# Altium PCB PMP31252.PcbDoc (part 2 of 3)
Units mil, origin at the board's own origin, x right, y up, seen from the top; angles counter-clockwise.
Board outline 4527.56 x 3188.98 mil, 6 copper layers (Top Layer, Layer 1, Layer 3, Layer 4, Layer 2, Bottom Layer), stack 32.112 mil thick; 215 components, 83 nets, 499 pads, 1248 vias.
Unrouted connection lines stored in the file: 2.
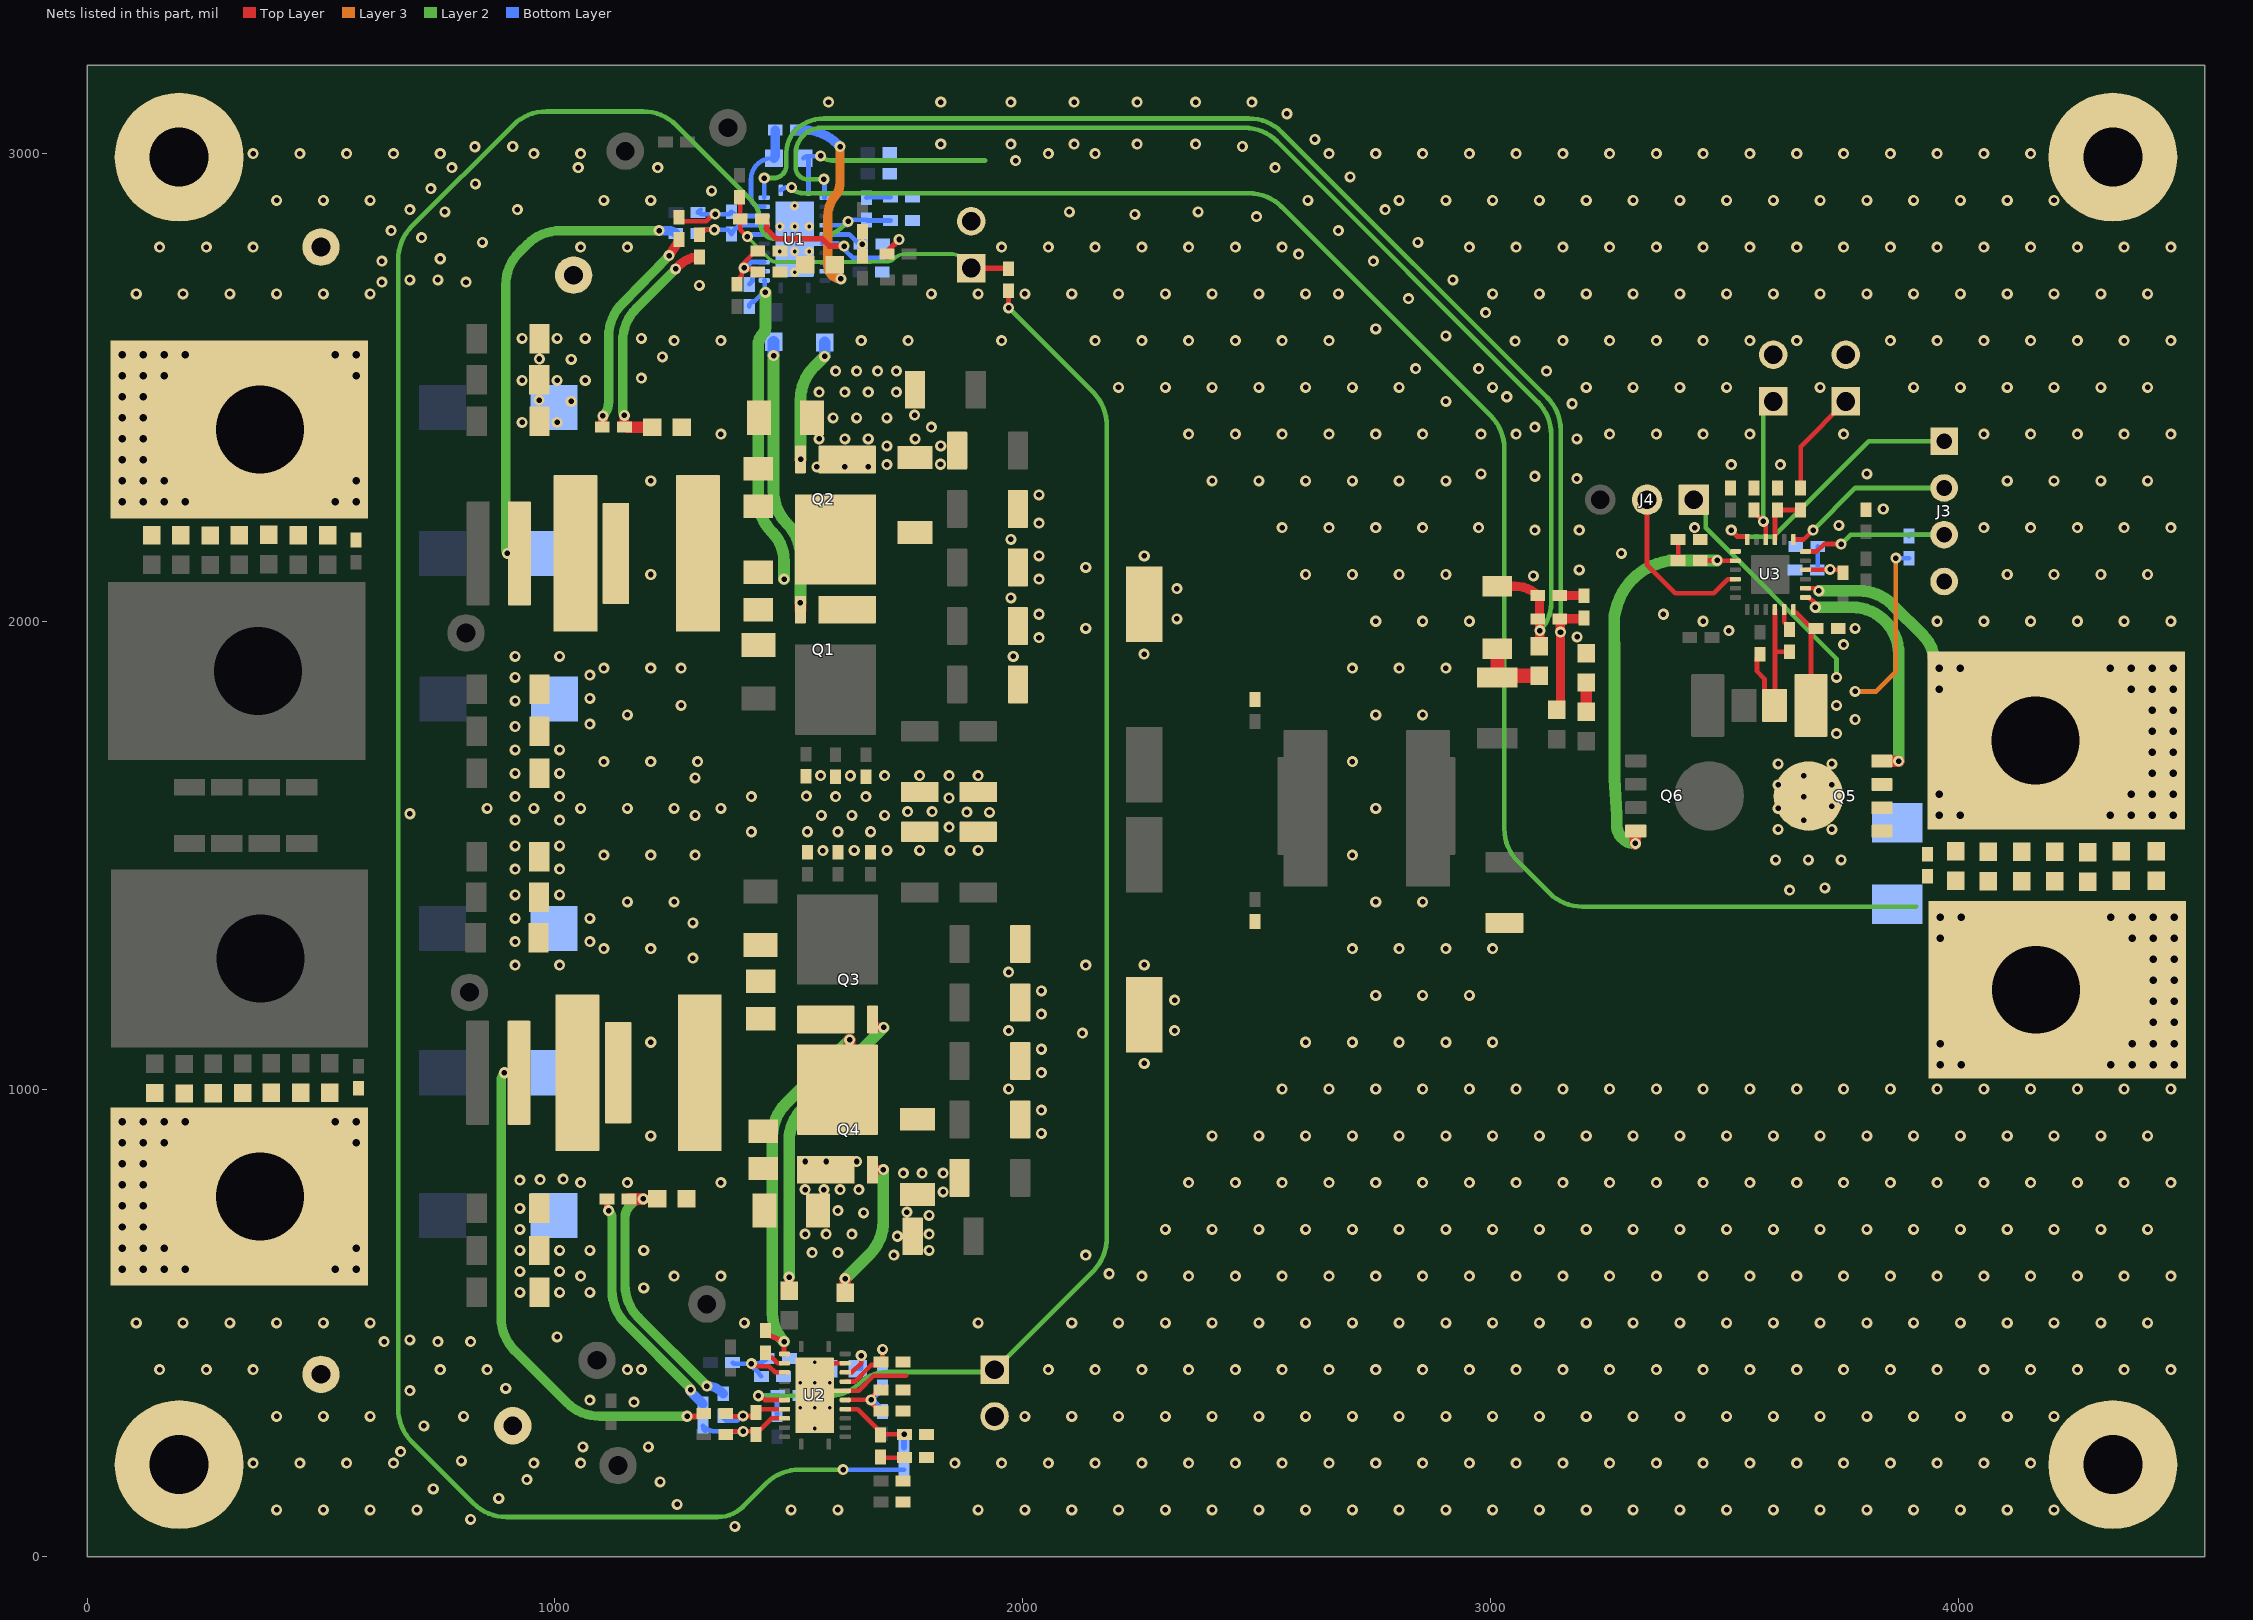
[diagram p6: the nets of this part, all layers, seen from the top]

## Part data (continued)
R24: library part CMP-0026619-3, "RES, 9.09 k, 1%, 0.063 W, AEC-Q200 Grade 0, 0402", Manufacturer=Vishay-Dale, Power_W=63mW, Supplier Part Number 1=541-9.09KLCT-ND, TempCo="100 ppm/C", Tolerance_%=1%, Value2=0.063W, Value_Code=9k09, ValueDisplayed=9.09k
R26 R27 R28 R29: library part CMP-0017276-1, "RES, 0, 1%, 0.25 W, 1206", Manufacturer="State of the Art", Power_W=250mW, TempCo="25 ppm/C", Tolerance_%=1%, Value2=0.25W, Value_Code=0
R30 R31 R32 R34: library part CMP-0017853-2, "RES, 110, 1%, 0.25 W, 1206", Manufacturer="Yageo America", Power_W=250mW, Supplier Part Number 1=311-110FRCT-ND, TempCo="100 ppm/C", Tolerance_%=1%, Value2=0.25W, Value_Code=110R, ValueDisplayed=110
R39 R59 R60 R61: library part CMP-0026753-1, "RES, 100 k, 1%, 0.063 W, AEC-Q200 Grade 0, 0402", Manufacturer="Stackpole Electronics Inc", Power_W=63mW, Supplier Part Number 1=RMCF0402FT100KCT-ND, TempCo="100 ppm/C", Tolerance_%=1%, Value2=0.063W, Value_Code=100k
R46: library part CMP-0026703-1, "RES, 49.9, 1%, 0.1 W, AEC-Q200 Grade 0, 0402", Manufacturer=Panasonic, Power_W=100mW, Supplier Part Number 1=P49.9LCT-ND, TempCo="100 ppm/C", Tolerance_%=1%, Value2=0.1W, Value_Code=49R9, ValueDisplayed=DNP
R47: library part CMP-0026605-2, "RES, 90.9 k, 1%, 0.063 W, AEC-Q200 Grade 0, 0402", Manufacturer=Vishay-Dale, Power_W=63mW, Supplier Part Number 1=541-90.9KLCT-ND, TempCo="100 ppm/C", Tolerance_%=1%, Value2=0.063W, Value_Code=90k9, ValueDisplayed=90.9k
R50 R53: library part CMP-0026196-2, "RES, 24.9 k, 1%, 0.063 W, AEC-Q200 Grade 0, 0402", Manufacturer=Vishay-Dale, Power_W=63mW, Supplier Part Number 1=541-24.9KLCT-ND, TempCo="100 ppm/C", Tolerance_%=1%, Value2=0.063W, Value_Code=24k9, ValueDisplayed=DNP
R55: library part CMP-0026685-1, "RES, 2.40 k, 1%, 0.1 W, AEC-Q200 Grade 0, 0402", Manufacturer=Panasonic, Power_W=100mW, Supplier Part Number 1=P2.40KLCT-ND, TempCo="100 ppm/C", Tolerance_%=1%, Value2=0.1W, Value_Code=2k40, ValueDisplayed=2.40k
R56: library part CMP-0093189-1, "500 µOhms ±1% 1W Chip Resistor 0805 (2012 Metric) Automotive AEC-Q200, Current Sense Metal Element", Digikey Part Number=738-CSSH0805FTL500CT-ND, Manufacturer="Stackpole Electronics", Operating Temperature Range="-55°C to +170°C", Power_W=1W, TempCo=100ppm/°C, Tolerance_%=1%
R57: library part CMP-0026763-1, "RES, 100, 1%, 0.063 W, AEC-Q200 Grade 0, 0402", Manufacturer="Stackpole Electronics Inc", Power_W=63mW, Supplier Part Number 1=RMCF0402JT100RCT-ND, TempCo="100 ppm/C", Tolerance_%=1%, Value2=0.063W, Value_Code=100R, ValueDisplayed=100
R62: library part CMP-0026092-3, "RES, 1.65 k, 1%, 0.063 W, AEC-Q200 Grade 0, 0402", Manufacturer=Vishay-Dale, Power_W=63mW, Supplier Part Number 1=541-1.65KLCT-ND, TempCo="100 ppm/C", Tolerance_%=1%, Value2=0.063W, Value_Code=1k65, ValueDisplayed=1.65k
R63: library part CMP-0025977-3, "RES, 11.5 k, 1%, 0.063 W, AEC-Q200 Grade 0, 0402", Manufacturer=Vishay-Dale, Power_W=63mW, Supplier Part Number 1=541-11.5KLCT-ND, TempCo="100 ppm/C", Tolerance_%=1%, Value2=0.063W, Value_Code=11k5, ValueDisplayed=11.5k
R65 R66: library part CMP-0078244-2, "RES, 30.0 k, 1%, 0.063 W, AEC-Q200 Grade 0, 0402", Manufacturer=Vishay-Dale, Power_W=63mW, Supplier Part Number 1=541-30.0KLCT-ND, TempCo="100 ppm/C", Tolerance_%=1%, Value2=0.063W, Value_Code=30k0, ValueDisplayed=30.0k
R68: library part CMP-0092536-1, "1 mOhms ±1% 3W Chip Resistor 2512 (6432 Metric) Automotive AEC-Q200, Current Sense, Moisture Resistant Metal Element", Digikey Part Number=HCS2512FT1L00CT-ND, Manufacturer="Stackpole Electronics", Operating Temperature Range="-55°C to +170°C", Power_W=3W, TempCo=100ppm/°C, Tolerance_%=1%
R69: library part CMP-0022716-3, "RES, 0.47, 1%, 0.1 W, AEC-Q200 Grade 0, 0603", Manufacturer=Panasonic, Power_W=100mW, Supplier Part Number 1=P.47AJCT-ND, TempCo="300 ppm/C", Tolerance_%=1%, Value2=0.1W, Value_Code=R470, ValueDisplayed=0.47
T1 T2 T3 T4 T5 T6: library part CMP-0055442-1, "Terminal 50A Lug", Manufacturer=Panduit, Supplier Part Number 1=CB35-36-CY-ND, Voltage_V=600V
TP1 TP5 TP8 TP10: library part CMP-0055137-2, "Test Point, Miniature, Red, TH", Color=Red, Manufacturer="Keystone Electronics", Supplier Part Number 1=36-5000-ND
TP2 TP6: library part CMP-0055141-2, "Test Point, Miniature, Yellow, TH", Color=Yellow, Manufacturer="Keystone Electronics", Supplier Part Number 1=36-5004-ND
TP3 TP7 TP9 TP11: library part CMP-0055138-2, "Test Point, Miniature, Black, TH", Color=Black, Manufacturer="Keystone Electronics", Supplier Part Number 1=36-5001-ND
TP4: library part CMP-0055140-2, "Test Point, Miniature, Orange, TH", Color=Orange, Manufacturer="Keystone Electronics", Supplier Part Number 1=36-5003-ND
U1 U2: library part CMP-0092804-1, "Automotive Synchronous Buck DC/DC Controller with Ultra-Low IQ, Adjustable, 0.8-36V, VQFN24", Manufacturer="Texas Instruments", Max Supply Voltage=42V, Min Supply Voltage=3.5V, Operating Temperature Range="-40°C to +150°C", Output Voltage=0.8-36V, Switching Frequency=100-2200kHz
U3: library part CMP-0001363-1, "Ideal Diode Controller with Integrated Short Circuit Protection with Fault Output", Manufacturer="Texas Instruments", Max Supply Voltage=65V, Min Supply Voltage=3V, Nominal Supply Current=550-600uA, Operating Temperature Range="-40°C to +150°C"

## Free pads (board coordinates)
  round 275.59 hole 125.98: 6(196.85,196.85) 6(196.85,2992.13) 6(4330.71,196.85) 6(4330.71,2992.13)

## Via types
v1: diameter 23.62, hole 11.81, Top Layer to Bottom Layer, tented both sides, 1061 vias
v2: diameter 32, hole 16, Top Layer to Bottom Layer, 168 vias
v3: diameter 19.68, hole 7.87, Top Layer to Bottom Layer, 16 vias
v4: diameter 23.62/23.62/23.62/23.62/23.62/23.62 (per signal layer), hole 11.81, Top Layer to Bottom Layer, tented both sides, 3 vias

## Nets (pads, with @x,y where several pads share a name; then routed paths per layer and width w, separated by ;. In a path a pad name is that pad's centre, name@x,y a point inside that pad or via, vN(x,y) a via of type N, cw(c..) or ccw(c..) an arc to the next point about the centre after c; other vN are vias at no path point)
AGND1: C24.2 C25.2 C26.2 NT3.1 R18.1 R19.1 R20.1 R21.1 R24.1 U1.7 | length 393.9
  Top Layer w12: R18.1@1443.62,2860 1447.56,2860 1453.37,2854.19 1453.37,2837.91 1473.78,2817.5 1571.45,2817.5 1586.75,2802.2 v1(1618.34,2802.2) ; R21.1@1710,2785 cw(c1722.07,2785) 1713.54,2793.54 v1(1736.16,2816.16)
  Layer 2 w10: v1(1618.34,2802.2) 1618.34,2805.65 cw(c1619.3,2805.65) v1@1619.3,2806.61
  Layer 3 w10: v1(1736.16,2816.16) cw(c1737.21,2815.11) v1@1737.21,2816.59
  Bottom Layer w10: NT3.1@1571.75,2807.44 1605.94,2807.44 ; v1(1618.34,2802.2) 1618.34,2803.51 1622.39,2803.51 1622.39,2790.98 1636.68,2776.69 1702.52,2776.69
AGND2: C45.2 C46.2 C47.2 NT4.1 R45.1 R47.1 R48.1 R53.2 U2.7 | length 149.2
  Top Layer w10: NT4.1@1614.76,355.09 1649.5,355.09 1681.19,386.77 1750.87,386.77
COMP2: C46.1 R54.2 R55.2 U2.5 | length 182.1
  Top Layer w10: U2.5@1620.83,315.47 1647.51,315.47 1689.06,273.93 1689.06,267.2 R55.2@1695.87,260.39 1697.24,261.77 C46.1@1747.24,261.77
  Bottom Layer w12: R54.2@1746.32,233.52 1746.32,260.2 cw(c1748.45,260.2) v1(1746.95,261.7)
ENABLE: J2.1 R33.1 R35.2 R67.2 U2.19 | length 3136.3
  Top Layer w10: v1@1442.99,341.57 1449.41,335.16 U2.19@1490.91,335.16 ; v1(1970,2670) R35.2@1970,2706.38
  Layer 2 w10: v1(1434.89,344.18) 1587.67,344.18 ccw(c1587.67,432.33) 1650,370 cw(c1710.36,309.64) 1710.36,395 1929.66,395 cw(c1929.66,382.27) J2.1@1938.66,391.27 ; J2.1@1940,400 2150.71,610.71 ccw(c2080,681.42) 2180,681.42 2180,2418.58 ccw(c2080,2418.58) 2150.71,2489.29 v1(1970,2670)
  Bottom Layer w10: v1(1434.89,344.18) 1435.3,344.59 R67.2@1475.97,344.59 ; R33.1@1475,303.62 1475,343.62 R67.2@1475.97,344.59 ; R67.2@1476.38,345 R67.2@1475.97,344.59
EXTCOMP: C24.1 R14.2 R54.1 U1.5 | length 5086.4
  Layer 2 w10: v1(1616.27,186.28) 1522.7,186.28 ccw(c1522.7,86.28) 1451.99,156.99 1402.5,107.5 cw(c1348.18,161.82) 1348.18,85 896.42,85 cw(c896.42,185) 825.71,114.29 694.29,245.71 cw(c765,316.42) 665,316.42 665,2773.58 cw(c765,2773.58) 694.29,2844.29 910.71,3060.71 cw(c981.42,2990) 981.42,3090 1188.58,3090 cw(c1188.58,2990) 1259.29,3060.71 1418.79,2901.21 cw(c1367.57,2850) 1440,2850 1440,2848.14 ccw(c1470.44,2848.14) 1470.44,2817.69 1548.34,2817.69 ccw(c1548.34,2917.69) 1619.05,2846.98 v1(1626.8,2854.74) ccw(c1623.53,2858.01) v1@1628.16,2858.01
  Bottom Layer w10: U1.5@1577.52,2846.69 1625,2846.69 ccw(c1617.38,2854.31) 1628.16,2854.31 1627.45,2854.53 v1(1626.8,2854.74) 1630.49,2854.74 1633.82,2858.07 R14.2@1666.14,2858.07 1667.52,2856.69 C24.1@1717.52,2856.69 ; v1(1616.27,186.28) R54.1@1746.32,186.28
FB1: R13.1 R16.1 R24.2 U1.6 | length 133.6
  Top Layer w10: R13.1@1657.52,2780.31 v1(1657.52,2805.91) R16.1@1657.52,2833.07
  Bottom Layer w10: U1.6@1577.52,2827.01 1629.65,2827.01 v1@1649.96,2806.69
FB2: R43.2 R45.2 R50.2 R53.1 U2.6 | length 188
  Top Layer w10: U2.6@1627.64,335.24 1627.77,335.37 v1(1675.89,335.37) ; R45.2@1693.31,311.77 1678.5,326.58 1678.5,332.76 v1(1675.89,335.37) ; R53.1@1697.07,356.71 1693.13,356.71 1678.5,342.07 1678.5,337.98 v1(1675.89,335.37)
  Bottom Layer w10: R50.2@1700.87,310.39 1700.87,314.33 1682.43,332.76 1678.5,332.76 v1(1675.89,335.37) 1677.02,335.37 1700.87,359.21 R43.2@1700.87,363.15
GND: C1.2 C2.1 C3.1 C4.1 C5.1 C6.1 C7.1 C8.1 C9.2 C16.2 C18.2 C19.2 C20.2 C21.2 C22.2 C27.2 C28.1 C29.1 C30.1 C31.1 C32.1 C33.1 C34.1 C36.1 C38.2 C39.2 C40.2 C41.2 C42.2 C43.2 C48.2 C49.2 C51.2 C52.2 C53.2 C54.1 C56.1 C57.2 C58.2 C59.2 C60.2 C61.2 C62.2 C63.2 C64.2 C65.2 C66.2 C67.2 C68.2 C69.2 C70.2 C71.2 C72.2 C73.2 C78.2 C79.2 C80.2 C81.2 C82.2 C83.2 C84.2 C85.2 C86.2 C87.2 C88.2 C89.2 C90.2 C91.2 C92.2 C93.2 C94.2 C95.2 C96.2 C97.2 C98.2 C99.2 C101.2 D1.2 D2.2 D3.1 J1.2 J2.2 J3.4 J5.2 J6.2 NT1.2 NT2.2 NT3.2 NT4.2 pad.6 Q2.1-2-3 Q4.1-2-3 R11.1 R31.1 R34.1 R42.1 R62.1 R63.1 R65.1 R66.1 R67.1 R69.1 T2.1 T4.1 T6.1 TP3.1 TP7.1 TP9.1 TP11.1 U1.10 U1.25 U2.10 U2.25 U3.13 | length 66.9
  Top Layer w10: v3(1555.87,415.87) 1555.87,413.9 U2.10@1620.83,413.9
  other v1: 1385,65 820,80 405,100 505,100 605,100 705,100 1505,100 1605,100 1905,100 2005,100 2105,100 2205,100 2305,100 2405,100 2505,100 2605,100 2705,100 2805,100 2905,100 3005,100 3105,100 3205,100 3305,100 3405,100 3505,100 3605,100 3705,100 3805,100 3905,100 4005,100 4105,100 4205,100 1261.48,111.89 880,125 740,145 1225,160 940,165 355,200 455,200 555,200 655,200 955,200 1055,200 1855,200 1955,200 2055,200 2155,200 2255,200 2355,200 2455,200 2555,200 2655,200 2755,200 2855,200 2955,200 3055,200 3155,200 3255,200 3355,200 3455,200 3555,200 3655,200 3755,200 3855,200 3955,200 4055,200 4155,200 800,205 670,225 1060,235 1200,235 720,280 405,300 505,300 605,300 805,300 2005,300 2105,300 2205,300 2305,300 2405,300 2505,300 2605,300 2705,300 2805,300 2905,300 3005,300 3105,300 3205,300 3305,300 3405,300 3505,300 3605,300 3705,300 3805,300 3905,300 4005,300 4105,300 4205,300 1169.16,330.76 1075,335 690,355 895,360 155,400 255,400 355,400 755,400 855,400 1155,400 1185,400 2055,400 2155,400 2255,400 2355,400 2455,400 2555,400 2655,400 2755,400 2855,400 2955,400 3055,400 3155,400 3255,400 3355,400 3455,400 3555,400 3655,400 3755,400 3855,400 3955,400 4055,400 4155,400 4255,400 4355,400 4455,400 635,460 750,460 820,460 689.96,463.6 1005,470 105,500 205,500 305,500 405,500 505,500 605,500 1405,500 1905,500 2105,500 2205,500 2305,500 2405,500 2505,500 2605,500 2705,500 2805,500 2905,500 3005,500 3105,500 3205,500 3305,500 3405,500 3505,500 3605,500 3705,500 3805,500 3905,500 4005,500 4105,500 4205,500 4305,500 4405,500 925,565 1010,565 1075,565 1190,575 1055,600 1255,600 1355,600 2255,600 2355,600 2455,600 2555,600 2655,600 2755,600 2855,600 2955,600 3055,600 3155,600 3255,600 3355,600 3455,600 3555,600 3655,600 3755,600 3855,600 3955,600 4055,600 4155,600 4255,600 4355,600 4455,600 2185,605 925,610 1010,610 1725,645 2135,645 1550,650 1605,650 925,655 1010,655 1075,655 1190,655 1800,655 1732.09,685.22 1535,690 1580,690 1635,690 1800,690 925,700 2305,700 2405,700 2505,700 2605,700 2705,700 2805,700 2905,700 3005,700 3105,700 3205,700 3305,700 3405,700 3505,700 3605,700 3705,700 3805,700 3905,700 4005,700 4105,700 4205,700 4305,700 4405,700 1800,730 1660,735 1752.77,736.64 1605,740 925,745 1830,780 1535,785 1575,785 1610,785 1650,785 1055,800 1155,800 1355,800 2355,800 2455,800 2555,800 2655,800 2755,800 2855,800 2955,800 3055,800 3155,800 3255,800 3355,800 3455,800 3555,800 3655,800 3755,800 3855,800 3955,800 4055,800 4155,800 4255,800 4355,800 4455,800 925,805 968.33,806.2 1017.8,807.22 1745,820 1785,820 1830,820 1535,845 1580,845 1645,845 1205,900 2405,900 2505,900 2605,900 2705,900 2805,900 2905,900 3005,900 3105,900 3205,900 3305,900 3405,900 3505,900 3605,900 3705,900 3805,900 3905,900 4005,900 4105,900 4205,900 4305,900 4405,900 2040,905 2040,955 1970,1000 2555,1000 2655,1000 2755,1000 2855,1000 2955,1000 3055,1000 3155,1000 3255,1000 3355,1000 3455,1000 3555,1000 3655,1000 3755,1000 3855,1000 3955,1000 4055,1000 4155,1000 4255,1000 4355,1000 4455,1000 2040,1035 2260,1055 2040,1085 1205,1100 2605,1100 2705,1100 2805,1100 2905,1100 3005,1100 2127.81,1119.37 1970,1125 2325,1125 2040,1160 2325,1190 2755,1200 2855,1200 2955,1200 2040,1210 1970,1250 915,1265 1010,1265 2135,1265 2260.01,1265.37 1295,1280 1105,1300 1205,1300 2705,1300 2805,1300 2905,1300 3005,1300 915,1315 1075,1315 1295,1355 915,1365 1075,1365 1155,1400 1255,1400 2755,1400 2855,1400 915,1415 1010,1415 915,1470 1010,1470 1105,1500 1205,1500 1300,1500 2705,1500 1573.09,1509.69 1640,1510 1710,1510 1780,1510 1845,1510 1905,1510 915,1520 1010,1520 1420,1550 1540,1550 1605,1550 1675,1550 1843.05,1560.12 915,1575 1010,1575 1300,1585 1570,1585 1635,1585 1705,1585 690.01,1588.52 1881.07,1592.03 1929.21,1591.61 1754.02,1593.09 1806.41,1593.09 855,1600 955,1600 1055,1600 1155,1600 1255,1600 1355,1600 2755,1600 1842.61,1622.18 915,1625 1010,1625 1420,1625 1600,1625 1665,1625 1537.89,1626 1300,1665 1568.2,1670.18 1631.88,1669.75 1705,1670 1780,1670 1842.83,1669.83 1905,1670 915,1675 1010,1675 1105,1700 1205,1700 1305,1700 2705,1700 915,1725 1010,1725 915,1775 1075,1780 1155,1800 2755,1800 2855,1800 1270,1820 915,1830 1075,1835 915,1880 1075,1885 1105,1900 1205,1900 1270,1900 2705,1900 2805,1900 2905,1900 915,1925 1010,1925 1980,1925 2259.99,1929.63 3755,1950 2035,1965 3185.69,1966.77 3510,1980 2135,1985 3780,1985 2755,2000 2855,2000 2955,2000 3455,2000 3955,2000 4055,2000 4155,2000 4255,2000 4355,2000 4455,2000 2330,2005 2035,2015 3370,2015 1975,2050 2330,2070 2035,2090 3091.85,2097.16 1205,2100 2605,2100 2705,2100 2805,2100 2905,2100 4105,2100 4205,2100 4305,2100 4405,2100 3190,2110 2135,2115 2035,2140 2260,2140 3280,2145 1975,2175 3095,2195 3190,2195 2555,2200 2655,2200 2755,2200 2855,2200 2975,2200 3436.69,2200.01 4055,2200 4155,2200 4255,2200 4355,2200 4455,2200 3745,2205 2035,2210 3840,2240 2035,2270 1205,2300 2405,2300 2505,2300 2605,2300 2705,2300 2805,2300 2905,2300 4105,2300 4205,2300 4305,2300 4405,2300 3185,2305 3095,2310 2980,2315 3805,2315 1560,2330 1620,2330 1670,2330 1710,2335 3515,2335 3620,2335 1824.43,2335.63 1710,2375 1825,2375 1565,2390 1620,2390 1670,2390 1770,2390 3185,2390 1355,2400 2355,2400 2455,2400 2555,2400 2655,2400 2755,2400 2855,2400 2980,2400 3055,2400 3255,2400 3355,2400 3455,2400 3555,2400 3755,2400 4055,2400 4155,2400 4255,2400 4355,2400 4455,2400 1805,2415 3095,2415 930,2425 1005,2425 1595,2435 1645,2435 1710,2435 1768.88,2440.57 3175,2465 1035,2470 2905,2470 966.1,2472.87 3035,2480 1565,2490 1620,2490 1670,2490 1730,2490 2205,2500 2305,2500 2405,2500 2505,2500 2605,2500 2705,2500 2805,2500 3005,2500 3205,2500 3305,2500 3405,2500 3505,2500 3705,2500 3905,2500 4005,2500 4105,2500 4205,2500 4305,2500 4405,2500 930,2515 1005,2515 1065,2515 1185,2520 1600,2535 1645,2535 1690,2535 1730,2535 3120,2535 2840,2540 2975,2540 1035,2560 967.09,2560.69 1230,2565 3052.79,2598.78 1255,2600 1355,2600 1655,2600 1755,2600 1955,2600 2155,2600 2255,2600 2355,2600 2455,2600 2555,2600 2655,2600 3155,2600 3255,2600 3355,2600 3455,2600 3555,2600 3655,2600 3855,2600 3955,2600 4055,2600 4155,2600 4255,2600 4355,2600 4455,2600 930,2605 1005,2605 1065,2605 1185,2605 2905,2610 2755,2625 2990,2660 2825,2690 105,2700 205,2700 305,2700 405,2700 505,2700 605,2700 1805,2700 1905,2700 2005,2700 2105,2700 2205,2700 2305,2700 2405,2700 2505,2700 2605,2700 2675,2700 3005,2700 3105,2700 3205,2700 3305,2700 3405,2700 3505,2700 3605,2700 3705,2700 3805,2700 3905,2700 4005,2700 4105,2700 4205,2700 4305,2700 4405,2700 1309,2718.23 630,2725 810,2725 690,2730 750,2730 2920,2730 630,2770 2750,2770 755,2775 2590,2785 155,2800 255,2800 355,2800 1055,2800 1155,2800 1955,2800 2055,2800 2155,2800 2255,2800 2355,2800 2455,2800 2555,2800 2955,2800 3055,2800 3155,2800 3255,2800 3355,2800 3455,2800 3555,2800 3655,2800 3755,2800 3855,2800 3955,2800 4055,2800 4155,2800 4255,2800 4355,2800 4455,2800 845,2810 2845,2810 715,2820 650,2835 2675,2835 2500,2865 2240,2870 765,2875 2100,2875 2375,2875 690,2880 920,2880 2775,2880 405,2900 505,2900 605,2900 1105,2900 1205,2900 2610,2900 2805,2900 2905,2900 3005,2900 3105,2900 3205,2900 3305,2900 3405,2900 3505,2900 3605,2900 3705,2900 3805,2900 3905,2900 4005,2900 4105,2900 4205,2900 1335,2920 735,2925 830,2935 2700,2950 780,2970 1050,2970 1220,2970 2540,2970 1985,2985 355,3000 455,3000 555,3000 655,3000 755,3000 955,3000 1055,3000 2055,3000 2155,3000 2655,3000 2755,3000 2855,3000 2955,3000 3055,3000 3155,3000 3255,3000 3355,3000 3455,3000 3555,3000 3655,3000 3755,3000 3855,3000 3955,3000 4055,3000 4155,3000 828.83,3014.51 910,3015 2470,3015 1825,3020 1975,3020 2110,3020 2245,3020 2370,3020 2625,3030 2565,3085 1585,3110 1825,3110 1975,3110 2110,3110 2245,3110 2370,3110 2490,3110
  other v2: 75,615 120,615 165,615 210,615 530,615 575,615 75,660 120,660 165,660 575,660 75,705 120,705 75,750 120,750 75,795 120,795 75,840 120,840 75,885 120,885 165,885 575,885 75,930 120,930 165,930 210,930 530,930 575,930 3961.83,1052.28 4006.83,1052.28 4326.83,1052.28 4371.83,1052.28 4416.83,1052.28 4461.83,1052.28 3961.83,1097.28 4371.83,1097.28 4416.83,1097.28 4461.83,1097.28 4416.83,1142.28 4461.83,1142.28 4416.83,1187.28 4461.83,1187.28 4416.83,1232.28 4461.83,1232.28 4416.83,1277.28 4461.83,1277.28 3961.83,1322.28 4371.83,1322.28 4416.83,1322.28 4461.83,1322.28 3961.83,1367.28 4006.83,1367.28 4326.83,1367.28 4371.83,1367.28 4416.83,1367.28 4461.83,1367.28 75,2255 120,2255 165,2255 210,2255 530,2255 575,2255 75,2300 120,2300 165,2300 575,2300 75,2345 120,2345 75,2390 120,2390 75,2435 120,2435 75,2480 120,2480 75,2525 120,2525 165,2525 575,2525 75,2570 120,2570 165,2570 210,2570 530,2570 575,2570
  other v3: 1555.87,274.13 1524.37,318.23 1555.87,318.23 1587.36,318.23 1524.37,371.77 1555.87,371.77 1587.36,371.77 1512.56,2746.3 1481.06,2790.39 1512.56,2790.39 1544.06,2790.39 1481.06,2843.94 1512.56,2843.94 1544.06,2843.94 1512.56,2888.03
NetC10_2: C10.2 C13.2 R3.1 U1.23 | length 2798.1
  Top Layer w20: C10.2@3149.97,1810.03 3149.97,1976.76 3149.28,1977.45 3149.28,2004.34 R3.1@3148.62,2005 3150,2005 3195.06,2005 ccw(c3195.06,2011.89) C13.2@3199.93,2007.02
  Layer 2 w10: v1(1447.6,2947.49) 1467.49,2947.49 ccw(c1467.49,2975) 1495,2975 1495,3001.72 cw(c1563.28,3001.72) 1515,3050 cw(c1575.36,2989.64) 1575.36,3075 2483.58,3075 cw(c2483.58,2975) 2554.29,3045.71 3121.05,2478.95 cw(c3050.34,2408.24) 3150.34,2408.24 3150.34,1977.19 v1(3149.94,1976.79)
  Bottom Layer w10: U1.23@1447.6,2905.75 v1(1447.6,2947.49)
NetC11_2: C11.2 C12.1 R1.2 | length 161
  Top Layer w20: C11.2@3015,1879.96 cw(c3023.55,1871.41) C11.2@3023.55,1883.5
  Top Layer w25: C12.1@3014.8,1941.12 C12.1@3023.96,1950.28
  Top Layer w30: C11.2@3014.8,1884 C12.1@3014.8,1941.12 ; C11.2@3023.55,1883.5 R1.2@3105,1883.5
NetC12_2: C12.2 R1.1 R2.2 R3.2 U1.2 | length 2706.3
  Top Layer w20: C12.2@3014.8,2074.98 3053.14,2074.98 cw(c3053.14,2006.76) R2.2@3101.38,2055 cw(c3092.63,2046.26) 3105,2046.26 3105,2005 3105,1980.6 v1(3105.7,1979.9) 3105.35,1979.56 3105.35,1946.84 R1.1@3105,1946.5
  Layer 2 w10: v1(1575,2945) 1540,2945 cw(c1540,2970) 1515,2970 1515,3000 cw(c1570,3000) 1570,3055 2473.58,3055 cw(c2473.58,2955) 2544.29,3025.71 3100.71,2469.29 cw(c3030,2398.58) 3130,2398.58 3130,2038.58 cw(c3047.02,2038.58) v1(3105.7,1979.9)
  Bottom Layer w10: v1(1575,2945) 1576.26,2943.74 1576.26,2905.83 1576.34,2905.75 U1.2@1577.52,2905.75
NetC13_1: C13.1 R2.1 | length 51.5
  Top Layer w20: R2.1@3148.62,2055 3198.15,2055 cw(c3198.15,2052.48) C13.1@3199.93,2054.26
NetC14_1: C14.1 C74.2 C75.1 D1.1 L2.1 L3.1 Q1.1-2-3 Q2.5-6-7-8 R8.1 U1.14 | length 708.8
  Layer 2 w25: v1(1450.23,2703.25) 1450.23,2627.64 cw(c1432.36,2627.64) 1445,2615 ccw(c1469.14,2590.86) 1435,2590.86 1435,2573.29 ccw(c1467.56,2567.91) 1434.56,2567.91 1434.56,2261.86 ccw(c1534.56,2261.86) 1463.85,2191.15 cw(c1400.71,2128.02) 1490,2128.02 v1(1490,2090)
  Bottom Layer w10: C14.1@1415.62,2672.92 1415.62,2676.86 1422.43,2683.67 1426.37,2683.67 1443.34,2700.64 1447.63,2700.64 v1(1450.23,2703.25) 1448.92,2704.57 1448.92,2728.5 1448.84,2728.58 U1.14@1447.6,2728.58
NetC14_2: C14.2 U1.15 | length 49.7
  Bottom Layer w10: C14.2@1415.62,2720.16 1422.43,2726.97 1422.43,2737.38 1433.24,2748.19 1447.52,2748.19 U1.15@1447.6,2748.27
NetC15_1: C15.1 L2.2 L3.2 R6.1 R17.2 R23.2 | length 1488.8
  Top Layer w12: v1(898.67,2145) R6.1@924.29,2145
  Top Layer w20: C15.1@1101.38,2415 1102.62,2416.24 v1(1102.62,2439) ; v1(1244.19,2781.62) 1263.19,2810.63 R17.2@1265,2816.38
  Layer 2 w20: v1(898.67,2145) cw(c907.53,2153.86) 895,2153.86 895,2718.58 cw(c995,2718.58) 924.29,2789.29 940.71,2805.71 cw(c1011.42,2735) 1011.42,2835 v1(1223.07,2835) ; v1(1102.62,2439) ccw(c1072.74,2468.88) 1115,2468.88 1115,2608.58 cw(c1215,2608.58) 1144.26,2679.26 ccw(c1130.16,2693.44) 1144.46,2679.46 v1(1244.19,2781.62)
  Bottom Layer w20: v1(1223.07,2835) 1244.06,2835 cw(c1244.06,2814.65) R23.2@1258.45,2829.04
NetC15_2: C15.2 R8.2 R15.2 | length 499.1
  Top Layer w20: C15.2@1148.62,2415 v1(1148.62,2440) ; v1(1258.34,2753.34) 1266.12,2761.12 cw(c1309,2718.23) R15.2@1309,2778.88
  Top Layer w25: C15.2@1155,2415 R8.2@1213.5,2415
  Layer 2 w20: v1(1148.62,2440) cw(c1157.37,2448.74) 1145,2448.74 1145,2598.58 cw(c1245,2598.58) 1174.29,2669.29 v1(1258.34,2753.34)
NetC16_1: C16.1 R7.1 U1.9 | length 450.9
  Layer 3 w20: v1(1609.73,3014.66) 1609.73,2939.27 cw(c1555.08,2939.27) 1606.21,2919.98 cw(c1555.08,2939.27) 1604.04,2915 ccw(c1653.81,2865.23) 1583.43,2865.23 1583.43,2760.34 ccw(c1611.61,2760.34) v1(1611.61,2732.16)
  Bottom Layer w10: U1.9@1588.46,2766.15 cw(c1587.36,2751.22) 1599.61,2759.83 cw(c1577.52,2733.87) 1611.61,2733.87 v1(1611.61,2732.16)
  Bottom Layer w20: R7.1@1518.62,3050 1532.97,3050 cw(c1532.97,2950) 1603.68,3020.71 v1(1609.73,3014.66)
NetC17_1: C17.1 R7.2 U1.22 | length 214.2
  Bottom Layer w10: U1.22@1447.6,2886.06 1438.94,2886.06 cw(c1438.94,2905.71) 1419.29,2905.71 1419.29,2944.51 cw(c1464.78,2944.51) 1453.82,2988.66 C17.1@1468.5,2990
  Bottom Layer w20: C17.1@1468.5,2990 ccw(c1461.57,2996.94) 1471.38,2996.94 R7.2@1471.38,3050
NetC17_2: C17.2 NT2.1 U1.1 | length 461
  Layer 2 w10: v1(1567.98,2995) ccw(c1592.13,3019.14) 1592.13,2985 NT2.1@1920,2985
  Bottom Layer w10: C17.2@1531.5,2990 cw(c1541.6,2979.9) 1541.6,2994.19 1566.02,2994.19 cw(c1567.98,2992.22) v1(1567.98,2995) ; U1.1@1542.09,2921.5 C17.2@1542.09,2990
NetC22_1: C22.1 R10.1 R11.2 U1.16 | length 169.1
  Top Layer w10: R10.1@1388.85,2723.92 1388.85,2727.86 1399.2,2738.21 1399.2,2760.93 1429.96,2791.69 R11.2@1433.9,2791.69 ; v1@1404.41,2753.12 1427.48,2753.12 C22.1@1433.9,2746.69
  Bottom Layer w10: v1(1404.41,2755.72) 1408.09,2755.72 1420.33,2767.95 U1.16@1447.6,2767.95
NetC23_1: C23.1 R15.1 R23.1 U1.20 | length 203.7
  Top Layer w10: R15.1@1309,2826.13 1309,2836.98 v1(1340.83,2836.98)
  Bottom Layer w10: R23.1@1306.18,2828.94 R23.1@1310.12,2828.94 ; R23.1@1307.03,2826.13 1310.97,2826.13 1321.54,2836.69 1370.71,2836.69 1377.52,2829.88 C23.1@1377.52,2828.07 1384.33,2838.26 ccw(c1381.03,2847.7) 1386.77,2839.51 1387.4,2839.96 ccw(c1380.56,2847.25) 1387.53,2840.08 1387.6,2840.14 cw(c1404.51,2822.88) 1406.51,2846.96 1409.08,2846.96 U1.20@1447.33,2846.96
NetC23_2: C23.2 R17.1 R25.1 U1.21 | length 253.9
  Top Layer w10: R17.1@1268.62,2872.37 cw(c1256.26,2872.37) R17.1@1265,2863.62 1265,2861.81 1271.81,2855 1323.52,2855 1338.83,2870.31 v1(1342.52,2870.31)
  Bottom Layer w10: R25.1@1306.18,2873.94 R25.1@1311.99,2879.75 ; R25.1@1307.03,2876.13 1307.7,2875.46 1312.85,2870.31 v1(1342.52,2870.31) 1372.52,2870.31 C23.2@1377.52,2875.32 ccw(c1399.1,2896.89) 1399.1,2866.38 U1.21@1447.6,2866.38
NetC26_1: C26.1 R14.1 | length 51.9
  Bottom Layer w10: R14.1@1666.14,2905.31 1667.52,2906.69 C26.1@1717.52,2906.69
NetC35_1: C35.1 C76.2 C77.1 D2.1 L4.1 L5.1 Q3.1-2-3 Q4.5-6-7-8 R38.1 U2.14 | length 907.9
  Top Layer w10: v1(1490,460) 1490,435.77 ccw(c1493.09,435.77) U2.14@1490.91,433.58
  Top Layer w12: C35.1@1450,483.62 1455.81,473.87 v1(1490,460)
  Top Layer w25: Q4.5-6-7-8@1603.94,998.5 1630,1024.57 v1(1630,1105)
  Layer 2 w25: v1(1490,460) cw(c1550.36,520.36) 1465,520.36 1465,898.58 cw(c1565,898.58) 1494.29,969.29 v1(1630,1105)
NetC35_2: C35.2 U2.15 | length 45.7
  Top Layer w10: C35.2@1450,436.38 1450,432.44 1456.81,425.63 1464.89,425.63 1476.55,413.98 U2.15@1484.09,413.98
NetC36_2: C36.2 U2.9 | length 94.2
  Top Layer w10: U2.9@1620.83,394.21 1635.11,394.21 1655,414.11 v1(1655,430)
  Bottom Layer w10: C36.2@1647.36,401.77 1655,401.77 v1(1655,430)
NetC37_1: C37.1 L4.2 L5.2 R37.1 R49.2 R51.2 | length 1581.8
  Top Layer w12: C37.1@1111.38,765 1111.38,748.74 ccw(c1123.74,748.74) v1(1115,740) ; v1(1282.66,300.35) 1283.22,299.79 1301.37,299.79 1302.17,300.58 1312.34,300.58 R51.2@1318.15,306.39
  Layer 2 w20: v4(892.09,1034.78) ccw(c909.22,1017.65) 885,1017.65 885,511.42 ccw(c985,511.42) 914.29,440.71 1025.36,329.64 ccw(c1096.07,400.35) 1096.07,300.35 v1(1282.66,300.35) ; v1(1115,740) cw(c1095.62,720.62) 1122.06,727.83 ccw(c1186.21,725) 1122,725 1122,569.42 ccw(c1222,569.42) 1151.29,498.71 1290,360 v1(1290,356.73)
  Bottom Layer w20: v1(1290,356.73) ccw(c1297.89,356.73) 1292.31,351.15 R49.2@1316.75,326.72
NetC37_2: C37.2 R38.2 R44.2 | length 559.7
  Top Layer w25: C37.2@1158.62,765 v1(1188.98,765)
  Layer 2 w20: v1(1188.98,765) ccw(c1188.98,731.26) 1165.12,755.12 1160.61,750.61 ccw(c1186.21,725) 1150,725 1150,581.42 ccw(c1250,581.42) 1179.29,510.71 v1(1325,365)
  Bottom Layer w20: v1(1325,365) cw(c1325,320.04) 1356.79,351.83 R44.2@1360,348.62
NetC43_1: C43.1 R40.1 R42.2 U2.16 | length 184.3
  Top Layer w10: v1@1419.99,410.93 v1(1419.99,412.81) ; v1@1427.37,407.63 1457.44,407.63 1470.78,394.29 1490.83,394.29 U2.16@1490.91,394.21
  Bottom Layer w10: R40.1@1380,415 ccw(c1385.28,420.28) 1385.28,412.81 v1(1419.99,412.81) ; R42.2@1441.08,385.68 1435.88,392.2 1435.88,392.91 1419.99,408.81 v1(1419.99,412.81) ; C43.1@1454.21,424.06 cw(c1427.05,451.22) 1427.05,412.81 v1(1419.99,412.81)
NetC44_1: C44.1 R44.1 R51.1 U2.20 | length 188.2
  Top Layer w10: R51.1@1365.4,306.39 1371.96,299.83 1400.97,299.83 v1(1402.2,301.06) 1423.19,301.06 1430,307.87 1430,308.66 1436.81,315.47 U2.20@1490.91,315.47
  Bottom Layer w10: R44.1@1360,301.38 1360,297.6 1366.81,290.79 1389.53,290.79 1399.8,301.06 v1(1402.2,301.06)
NetC44_2: C44.2 R49.1 R52.1 U2.21 | length 248.3
  Top Layer w10: R52.1@1365.25,261.77 1372.02,268.54 v1@1402.11,268.54 ; v1(1402.62,268.04) 1423.34,268.04 C44.2@1430,261.38 1430,265.32 1436.81,272.13 1440.43,272.13 1464.09,295.79 U2.21@1490.91,295.79
  Bottom Layer w10: R49.1@1321.26,268.59 cw(c1332.14,279.47) R49.1@1316.75,279.47 ccw(c1344.35,307.08) 1344.35,268.04 v1(1402.62,268.04)
NetC45_1: C45.1 R43.1 U2.8 | length 154.5
  Top Layer w10: U2.8@1620.83,374.53 1620.91,374.61 1640.96,374.61 1676.31,409.96 1690.43,409.96 1700.87,420.39 v1(1700.87,443.14)
  Bottom Layer w10: R43.1@1700.87,410.39 v1(1700.87,443.14)
NetC47_1: C47.1 R55.1 | length 51.9
  Top Layer w10: R55.1@1695.87,213.15 1697.24,211.77 C47.1@1747.24,211.77
NetC48_1: C48.1 C92.1 C93.1 C94.1 C95.1 C96.1 C97.1 C98.1 D3.2 Q5.1 Q5.2 Q5.3 T5.1 U3.2 | length 349
  Top Layer w10: U3.2@3673.31,2070.47 3696.82,2070.47 v1(3702.29,2065)
  Layer 2 w25: v1(3702.29,2065) 3788.58,2065 cw(c3788.58,1965) 3859.29,2035.71 3926.37,1968.63 cw(c3874.08,1916.34) T5.1@3948.03,1916.34
  other v2: 3960,1585 4005,1585 4325,1585 4370,1585 4415,1585 4460,1585 3960,1630 4370,1630 4415,1630 4460,1630 4415,1675 4460,1675 4415,1720 4460,1720 4415,1765 4460,1765 4415,1810 4460,1810 3960,1855 4370,1855 4415,1855 4460,1855 3960,1900 4005,1900 4325,1900 4370,1900 4415,1900 4460,1900
NetC49_1: C49.1 C50.1 J4.1 Q5.5 R56.1 R58.2 R59.2 R68.1 U3.22 U3.24 | length 1495.6
  Top Layer w10: R58.2@3581.83,1935 R58.2@3576.18,1929.35 3570,1923.17 3570,1892.91 3585.91,1877.01 3585.91,1841.57 R56.1@3607.48,1820 3608.35,1820.87 3608.35,1935 ; U3.22@3608.35,2025.2 3608.35,1935 ; C50.1@3640,1935 3608.35,1935 ; U3.24@3647.72,2025.2 3647.72,2018.46 3647.8,2018.39 3654.53,2018.39 3681.1,1991.81 3689.57,1991.81 C49.1@3696.38,1985 3692.44,1985 3685.63,1978.19 3685.63,1820.39 R68.1@3685.24,1820
  Layer 2 w10: J4.1@3435,2260 3460.53,2234.47 3460.53,2199.47 3740,1920 v1(3740,1880)
  Layer 3 w10: v1(3780,1850) 3825,1850 3866.84,1891.84 v1(3866.84,2135)
  Bottom Layer w10: v1(3866.84,2135) R59.2@3895,2135
  other v1: 3640,1425 3715,1430 3610,1490 3680,1490 3750,1490 3615,1555 3730,1555 3670,1575 3615,1600 3730,1605 3670.37,1625.3 3615,1650 3730,1650 3670,1670 3615,1695 3730,1695 3740,1760 3780,1790 3740,1820
NetC50_2: C50.2 U3.23 | length 47.9
  Top Layer w10: U3.23@3628.03,2025.2 3628.03,1998.15 3640,1986.18 C50.2@3640,1982.24
NetC51_1: C51.1 R57.1 | length 45
  Top Layer w10: R57.1@3401.38,2130 C51.1@3401.38,2175
NetC52_1: C52.1 R64.2 U3.9 | length 115.1
  Top Layer w10: U3.9@3608.35,2174.8 3608.43,2174.88 3608.43,2232.68 C52.1@3613.5,2237.76 R64.2@3663.5,2237.76
NetC53_1: C53.1 R60.1 R63.2 U3.4 | length 162.1
  Top Layer w10: U3.4@3673.31,2109.84 3673.39,2109.92 3725.72,2109.92 v1(3726.51,2110.71) ; v1@3726.33,2109.84 3747.28,2109.84 R60.1@3753.5,2103.62
  Bottom Layer w10: C53.1@3700,2160 3700,2111.38 R63.2@3698.62,2110 3698.98,2110.35 3726.16,2110.35 v1(3726.51,2110.71)
NetC55_2: C55.2 R69.2 | length 62.6
  Top Layer w25: C55.2@3205,1806.5 R69.2@3205.01,1869.06
NetC74_1: C74.1 R30.1
NetC75_2: C75.2 R31.2
NetC76_1: C76.1 R32.1
NetC77_2: C77.2 R34.2
NetC102_2: 
NetJ1_1: J1.1 R5.1 R18.2 R35.1 U1.19 | length 713
  Top Layer w10: R5.1@1396.38,2905 R18.2@1396.38,2860 1396.38,2837.24 v1(1411.46,2822.15)
  Top Layer w12: J1.1@1890,2755 1966.67,2755 cw(c1966.67,2750.3) R35.1@1970,2753.62
  Layer 2 w8: v1(1411.46,2822.15) 1460.57,2773.05 ccw(c1472.41,2784.9) 1472.41,2768.14 1671.17,2768.14 ccw(c1671.17,2825.83) 1679.17,2768.7 1709.79,2768.7 ccw(c1709.79,2790.21) 1725,2775 cw(c1749.14,2750.86) 1749.14,2785 1850,2785 cw(c1850,2760.86) 1867.07,2777.93 J1.1@1890,2755
  Bottom Layer w10: v1@1420,2827.01 U1.19@1447.6,2827.01
NetJ3_1: J3.1 U3.12 | length 591.7
  Top Layer w10: v1(3515,2195) 3529.21,2180.79 3549.21,2180.79 3549.29,2180.71 U3.12@3549.29,2174.8
  Layer 2 w10: v1(3515,2195) 3529.29,2180.71 3604.49,2180.71 3808.78,2385 J3.1@3970,2385
NetJ3_2: J3.2 U3.7 | length 367.9
  Top Layer w10: U3.7@3647.72,2174.8 3669.8,2174.8 v1(3690,2195)
  Layer 2 w10: v1(3690,2195) 3780,2285 J3.2@3970,2285
NetJ3_3: J3.3 R59.1 U3.6 | length 387.7
  Top Layer w10: U3.6@3673.31,2149.21 3698.06,2149.21 3713.85,2165 v1(3750,2165)
  Layer 2 w10: v1(3750,2165) 3770,2185 J3.3@3970,2185
  Bottom Layer w10: R59.1@3895,2182.24 3897.76,2185 J3.3@3970,2185
NetJ4_2: J4.2 U3.16 | length 366
  Top Layer w10: J4.2@3335,2260 3335,2120 3395,2060 3477.13,2060 3507.21,2090.08 3523.62,2090.08 U3.16@3523.7,2090.16
NetJ5_1: J5.1 R64.1 | length 225
  Top Layer w10: R64.1@3663.5,2285 3663.5,2373.5 J5.1@3760,2470
NetJ6_1: J6.1 R65.2 U3.10 | length 342.2
  Top Layer w10: R65.2@3563.5,2237.76 3563.5,2233.82 v1(3583.61,2213.71) 3589.08,2208.24 3589.08,2202.03 3588.66,2201.61 U3.10@3588.66,2174.8
  Layer 2 w10: v1(3583.61,2213.71) 3583.61,2448.61 cw(c3605,2448.61) J6.1@3605,2470
NetNT1_1: NT1.1 U1.24 | length 3575.3
  Layer 2 w10: v1(1506.37,2927.4) ccw(c1506.37,2924.11) 1504.05,2926.44 ccw(c1531.66,2954.05) 1531.66,2915 2483.58,2915 cw(c2483.58,2815) 2554.29,2885.71 3000.71,2439.29 cw(c2930,2368.58) 3030,2368.58 3030,1556.42 ccw(c3130,1556.42) 3059.29,1485.71 3125.71,1419.29 ccw(c3196.42,1490) 3196.42,1390 NT1.1@3910,1390
  Bottom Layer w10: U1.24@1483.03,2921.5 cw(c1497.29,2907.24) 1497.29,2927.4 v1(1506.37,2927.4)
NetQ1_4: Q1.4 R4.2 | length 587.9
  Top Layer w25: Q1.4@1524.96,2024.84 v1(1524.96,2040)
  Layer 2 w25: v1(1467.56,2567.91) 1467.56,2278.86 ccw(c1567.56,2278.86) 1496.85,2208.15 cw(c1428.98,2140.28) 1524.96,2140.28 v1(1524.96,2040)
  Bottom Layer w25: v1(1467.56,2567.91) R4.2@1467.56,2597.44
NetQ2_4: Q2.4 R9.2 | length 267.1
  Top Layer w25: Q2.4@1524.96,2345.94 v1(1525.22,2346.21)
  Layer 2 w25: v1(1525.22,2346.21) 1525.22,2473.46 cw(c1625.22,2473.46) 1554.51,2544.17 v1(1576.75,2566.41)
  Bottom Layer w25: v1(1576.75,2566.41) R9.2@1576.75,2595.94
NetQ3_4: Q3.4 R36.2 | length 680.8
  Top Layer w20: R36.2@1500.87,568.27 v1(1500.87,597.8) ; Q3.4@1678.94,1148.54 1678.94,1134.49 1680.75,1132.68 1701.95,1132.68 v1(1702.64,1131.99)
  Layer 2 w25: v1(1500.87,597.8) 1500.87,888.79 cw(c1598.1,888.79) 1529.34,957.54 v1@1702.64,1130.84
NetQ4_4: Q4.4 R41.2 | length 315.9
  Top Layer w20: Q4.4@1678.94,827.44 1702.19,827.44 v1(1702.19,827.68)
  Top Layer w25: v1(1620.74,594.42) 1620.87,594.29 R41.2@1620.87,564.76
  Layer 2 w25: v1(1620.74,594.42) 1672.9,646.57 ccw(c1602.19,717.28) 1702.19,717.28 v1(1702.19,827.68)
NetQ5_4: Q5.4 U3.1 | length 533.6
  Top Layer w10: U3.1@3673.31,2050.79 3674.21,2050.79 cw(c3674.21,2030) 3683.71,2048.49 3692.01,2040.19 3692.33,2040.19 cw(c3674.21,2030) v1(3695,2030)
  Top Layer w25: Q5.4@3837.04,1701.27 3837.3,1701.01 v1(3873,1701.01)
  Layer 2 w25: v1(3695,2030) 3773,2030 cw(c3773,1930) 3873,1930 v1(3873,1701.01)
NetQ6_4: Q6.4 R57.2 U3.14 | length 893.2
  Top Layer w10: R57.2@3448.62,2130 v1(3485,2130) 3485,2129.53 U3.14@3523.7,2129.53
  Top Layer w25: v1(3310,1525) 3310,1550.66 cw(c3310.94,1550.66) Q6.4@3310.94,1551.61
  Layer 2 w25: v1(3310,1525) cw(c3310,1565) 3270,1565 3270,1585.71 3265.29,1663.43 3265.29,1953.14 3265,1953.43 3265,2011.57 3269.01,2027.65 cw(c3400,1995) 3367.35,2125.99 3383.43,2130 v1(3485,2130)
